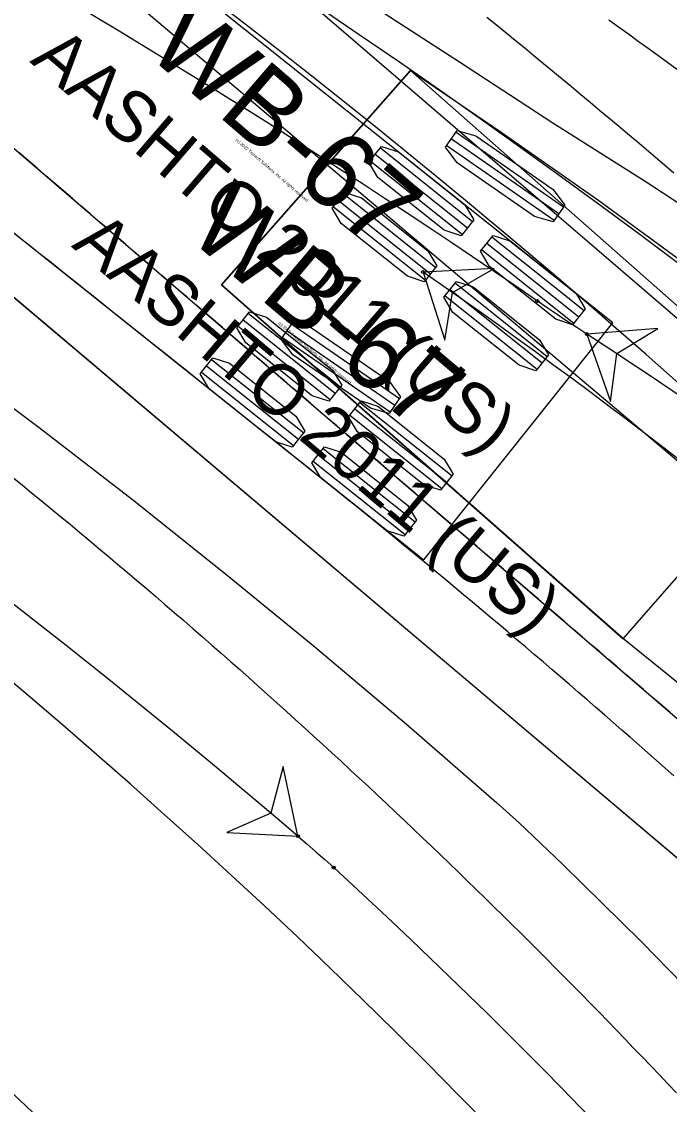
# Model space of a CAD drawing. Extents: x 2175591 to 2194071, y 76570 to 86955.
# Drawn here: x 2192868.19 to 2192886.34, y 86887.24 to 86917.59 of the extents above; entities that cross this region are included whole.
import ezdxf

# ---------------------------------------------------------------- set-up
doc = ezdxf.new("R2010")
doc.units = 0
doc.layers.add('-NOPLT', color=7, linetype='Continuous')
doc.layers.add('C-UTIL-STRM-TEXT', color=7, linetype='Continuous')

msp = doc.modelspace()

# ---------------------------------------------------------------- linework, layer by layer
at = {"layer": '-NOPLT'}
for p, q in [((2192884.758, 86909.148), (2192843.326, 86942.199)), ((2192838.025, 86935.555), (2192879.458, 86902.504)), ((2192898.388, 86899.098), (2192858.201, 86933.653)), ((2192852.66, 86927.208), (2192892.847, 86892.653)), ((2192878.244, 86914.052), (2192880.824, 86911.994)), ((2192877.958, 86913.693), (2192880.538, 86911.635)), ((2192878.101, 86913.873), (2192880.681, 86911.815)), ((2192877.072, 86912.583), (2192879.652, 86910.525)), ((2192877.215, 86912.762), (2192879.795, 86910.704)), ((2192876.929, 86912.403), (2192879.509, 86910.346)), ((2192881.228, 86911.378), (2192883.808, 86909.32)), ((2192881.371, 86911.557), (2192883.951, 86909.499)), ((2192881.085, 86911.199), (2192883.665, 86909.141)), ((2192880.199, 86910.088), (2192882.779, 86908.03)), ((2192880.342, 86910.267), (2192882.922, 86908.209)), ((2192880.056, 86909.909), (2192882.636, 86907.851)), ((2192874.401, 86909.234), (2192876.981, 86907.176)), ((2192874.544, 86909.413), (2192877.124, 86907.355)), ((2192879.458, 86902.504), (2192884.758, 86909.148)), ((2192874.258, 86909.055), (2192876.838, 86906.997)), ((2192873.372, 86907.944), (2192875.952, 86905.886)), ((2192873.515, 86908.123), (2192876.095, 86906.066)), ((2192873.229, 86907.765), (2192875.809, 86905.707)), ((2192877.528, 86906.74), (2192880.108, 86904.682)), ((2192877.671, 86906.919), (2192880.251, 86904.861)), ((2192877.385, 86906.561), (2192879.965, 86904.503)), ((2192876.642, 86905.629), (2192879.222, 86903.571)), ((2192876.356, 86905.271), (2192878.936, 86903.213)), ((2192876.499, 86905.45), (2192879.079, 86903.392))]:
    msp.add_line(p, q, dxfattribs=at)
for points in [[(2192881.23, 86917.714), (2192881.495, 86917.5), (2192881.76, 86917.285), (2192882.024, 86917.07), (2192882.288, 86916.854), (2192882.552, 86916.638), (2192882.815, 86916.422), (2192883.078, 86916.205), (2192883.341, 86915.988), (2192883.603, 86915.77), (2192883.865, 86915.552), (2192884.127, 86915.334), (2192884.388, 86915.115), (2192884.649, 86914.896), (2192884.91, 86914.677), (2192885.171, 86914.457), (2192885.431, 86914.237), (2192885.691, 86914.016), (2192885.95, 86913.795), (2192886.209, 86913.574), (2192886.468, 86913.352)], [(2192884.641, 86917.646), (2192884.918, 86917.448), (2192885.194, 86917.249), (2192885.47, 86917.049), (2192885.745, 86916.849), (2192886.021, 86916.649), (2192886.296, 86916.449), (2192886.571, 86916.248)], [(2192886.351, 86898.238), (2192886.106, 86898.449), (2192885.861, 86898.66), (2192885.616, 86898.87), (2192885.371, 86899.081), (2192885.126, 86899.292), (2192884.881, 86899.503), (2192884.635, 86899.713), (2192884.39, 86899.924), (2192884.145, 86900.135), (2192883.9, 86900.346), (2192883.655, 86900.557), (2192883.409, 86900.768), (2192883.164, 86900.979), (2192882.919, 86901.19), (2192882.673, 86901.401), (2192882.428, 86901.612), (2192882.182, 86901.823), (2192881.937, 86902.034), (2192881.692, 86902.245), (2192881.446, 86902.456), (2192881.201, 86902.667), (2192880.955, 86902.878), (2192880.71, 86903.089), (2192880.464, 86903.3), (2192880.218, 86903.512), (2192879.973, 86903.723), (2192879.727, 86903.934), (2192879.481, 86904.145), (2192879.235, 86904.357), (2192878.989, 86904.568), (2192878.744, 86904.779), (2192878.498, 86904.991), (2192878.252, 86905.202), (2192878.006, 86905.414), (2192877.76, 86905.625), (2192877.514, 86905.837), (2192877.268, 86906.049), (2192877.021, 86906.26), (2192876.775, 86906.472), (2192876.529, 86906.684), (2192876.283, 86906.896), (2192876.036, 86907.108), (2192875.79, 86907.319), (2192875.543, 86907.531), (2192875.297, 86907.743), (2192875.05, 86907.956), (2192874.803, 86908.167), (2192874.557, 86908.38), (2192874.31, 86908.592), (2192874.063, 86908.804), (2192873.816, 86909.016), (2192873.569, 86909.229), (2192873.322, 86909.441), (2192873.075, 86909.654), (2192872.828, 86909.866), (2192872.581, 86910.079), (2192872.334, 86910.291), (2192872.086, 86910.504), (2192871.839, 86910.716), (2192871.592, 86910.929), (2192871.344, 86911.142), (2192871.097, 86911.355), (2192870.849, 86911.567), (2192870.602, 86911.78), (2192870.354, 86911.993), (2192870.107, 86912.206), (2192869.859, 86912.419), (2192869.611, 86912.632), (2192869.364, 86912.845), (2192869.116, 86913.058), (2192868.868, 86913.271), (2192868.621, 86913.484), (2192868.373, 86913.697), (2192868.125, 86913.91)], [(2192886.468, 86896.451), (2192886.225, 86896.666), (2192885.982, 86896.88), (2192885.739, 86897.095), (2192885.496, 86897.309), (2192885.252, 86897.523), (2192885.008, 86897.736), (2192884.764, 86897.95), (2192884.52, 86898.162), (2192884.275, 86898.375), (2192884.03, 86898.587), (2192883.785, 86898.799), (2192883.54, 86899.011), (2192883.294, 86899.222), (2192883.048, 86899.434), (2192882.802, 86899.644), (2192882.556, 86899.855), (2192882.309, 86900.065), (2192882.062, 86900.275), (2192881.815, 86900.484), (2192881.568, 86900.693), (2192881.32, 86900.902), (2192881.072, 86901.111), (2192880.824, 86901.319), (2192880.575, 86901.527), (2192880.327, 86901.734), (2192880.078, 86901.942), (2192879.829, 86902.149), (2192879.579, 86902.355), (2192879.329, 86902.561), (2192879.079, 86902.767), (2192878.829, 86902.973), (2192878.579, 86903.178), (2192878.328, 86903.383), (2192878.077, 86903.588), (2192877.826, 86903.792), (2192877.574, 86903.997), (2192877.323, 86904.2), (2192877.071, 86904.404), (2192876.818, 86904.607), (2192876.566, 86904.809), (2192876.313, 86905.012), (2192876.06, 86905.214), (2192875.807, 86905.416), (2192875.554, 86905.618), (2192875.301, 86905.819), (2192875.048, 86906.021), (2192874.795, 86906.223), (2192874.542, 86906.425), (2192874.289, 86906.627), (2192874.036, 86906.829), (2192873.783, 86907.03), (2192873.53, 86907.232), (2192873.277, 86907.434), (2192873.024, 86907.636), (2192872.771, 86907.838), (2192872.518, 86908.04), (2192872.265, 86908.241), (2192872.012, 86908.443), (2192871.759, 86908.645), (2192871.506, 86908.847), (2192871.253, 86909.049), (2192871, 86909.25), (2192870.747, 86909.452), (2192870.494, 86909.654), (2192870.241, 86909.856), (2192869.988, 86910.058), (2192869.735, 86910.259), (2192869.482, 86910.461), (2192869.229, 86910.663), (2192868.976, 86910.865), (2192868.723, 86911.067), (2192868.47, 86911.269), (2192868.217, 86911.47), (2192867.964, 86911.672)], [(2192867.931, 86904.827), (2192868.201, 86904.607), (2192868.471, 86904.387), (2192868.74, 86904.167), (2192869.009, 86903.946), (2192869.278, 86903.725), (2192869.546, 86903.503), (2192869.814, 86903.281), (2192870.081, 86903.058), (2192870.348, 86902.835), (2192870.615, 86902.611), (2192870.881, 86902.387), (2192871.146, 86902.162), (2192871.412, 86901.937), (2192871.676, 86901.711), (2192871.941, 86901.485), (2192872.205, 86901.258), (2192872.469, 86901.031), (2192872.732, 86900.804), (2192872.995, 86900.576), (2192873.257, 86900.347), (2192873.519, 86900.118), (2192873.78, 86899.888), (2192874.041, 86899.658), (2192874.302, 86899.428), (2192874.562, 86899.197), (2192874.822, 86898.965), (2192875.082, 86898.733), (2192875.341, 86898.501), (2192875.599, 86898.268), (2192875.857, 86898.035), (2192876.115, 86897.801), (2192876.372, 86897.566), (2192876.629, 86897.332), (2192876.885, 86897.096), (2192877.141, 86896.861), (2192877.397, 86896.624), (2192877.652, 86896.388), (2192877.907, 86896.151), (2192878.161, 86895.913), (2192878.415, 86895.675), (2192878.668, 86895.436), (2192878.921, 86895.197), (2192879.174, 86894.958), (2192879.426, 86894.718), (2192879.677, 86894.477), (2192879.928, 86894.237), (2192880.179, 86893.995), (2192880.429, 86893.754), (2192880.679, 86893.511), (2192880.929, 86893.269), (2192881.178, 86893.025), (2192881.426, 86892.782), (2192881.674, 86892.538), (2192881.922, 86892.293), (2192882.169, 86892.048), (2192882.416, 86891.803), (2192882.662, 86891.557), (2192882.908, 86891.311), (2192883.153, 86891.064), (2192883.398, 86890.817), (2192883.643, 86890.569), (2192883.887, 86890.321), (2192884.13, 86890.072), (2192884.373, 86889.823), (2192884.616, 86889.574), (2192884.858, 86889.324), (2192885.1, 86889.073), (2192885.341, 86888.822), (2192885.582, 86888.571), (2192885.822, 86888.319), (2192886.062, 86888.067), (2192886.302, 86887.815), (2192886.541, 86887.562)]]:
    msp.add_lwpolyline(points, dxfattribs=at)
for points in [[(2192877.923, 86913.649), (2192878.279, 86914.096), (2192878.748, 86913.943), (2192880.606, 86912.461), (2192880.859, 86912.038), (2192880.503, 86911.591), (2192880.034, 86911.744), (2192878.176, 86913.226)], [(2192876.894, 86912.359), (2192877.251, 86912.806), (2192877.719, 86912.653), (2192879.577, 86911.171), (2192879.83, 86910.748), (2192879.474, 86910.301), (2192879.005, 86910.455), (2192877.148, 86911.936)], [(2192881.05, 86911.155), (2192881.406, 86911.602), (2192881.875, 86911.448), (2192883.732, 86909.967), (2192883.986, 86909.544), (2192883.629, 86909.097), (2192883.161, 86909.25), (2192881.303, 86910.732)], [(2192880.021, 86909.865), (2192880.377, 86910.312), (2192880.846, 86910.158), (2192882.704, 86908.677), (2192882.957, 86908.254), (2192882.601, 86907.807), (2192882.132, 86907.96), (2192880.274, 86909.442)], [(2192874.223, 86909.011), (2192874.579, 86909.458), (2192875.048, 86909.304), (2192876.905, 86907.823), (2192877.159, 86907.4), (2192876.802, 86906.953), (2192876.334, 86907.106), (2192874.476, 86908.588)], [(2192873.194, 86907.721), (2192873.55, 86908.168), (2192874.019, 86908.015), (2192875.877, 86906.533), (2192876.13, 86906.11), (2192875.774, 86905.663), (2192875.305, 86905.816), (2192873.447, 86907.298)], [(2192877.35, 86906.516), (2192877.706, 86906.963), (2192878.175, 86906.81), (2192880.032, 86905.328), (2192880.286, 86904.905), (2192879.929, 86904.458), (2192879.461, 86904.612), (2192877.603, 86906.093)], [(2192876.321, 86905.226), (2192876.677, 86905.673), (2192877.146, 86905.52), (2192879.003, 86904.038), (2192879.257, 86903.616), (2192878.9, 86903.168), (2192878.432, 86903.322), (2192876.574, 86904.804)]]:
    msp.add_lwpolyline(points, close=True, dxfattribs=at)
for centre, radius, start, end in [((2192733.134, 86734.566), 231.18, 31.07167, 66.3451), ((2192748.446, 86757.375), 185.351, 28.75355, 79.22293), ((2192746.129, 86724.49), 233.336, 23.25976, 66.11585)]:
    msp.add_arc(centre, radius, start, end, dxfattribs=at)
at = {"layer": 'C-UTIL-STRM-TEXT'}
for p, q in [((2192899.695, 86894.172), (2192859.224, 86928.392)), ((2192853.736, 86921.902), (2192894.207, 86887.681)), ((2192879.084, 86916.218), (2192873.793, 86910.218)), ((2192890.334, 86906.296), (2192879.084, 86916.218)), ((2192880.235, 86914.308), (2192883.245, 86912.214)), ((2192880.365, 86914.496), (2192883.375, 86912.402)), ((2192880.104, 86914.119), (2192883.114, 86912.026)), ((2192873.793, 86910.218), (2192885.043, 86900.296)), ((2192873.793, 86910.218), (2192873.793, 86910.218)), ((2192875.629, 86908.922), (2192878.648, 86906.841)), ((2192875.759, 86909.111), (2192878.778, 86907.03)), ((2192875.499, 86908.734), (2192878.518, 86906.653)), ((2192885.043, 86900.296), (2192886.74, 86902.221))]:
    msp.add_line(p, q, dxfattribs=at)
for points in [[(2192917.573, 86863.028), (2192915.761, 86865.28), (2192913.888, 86867.533), (2192912.022, 86869.708), (2192910.323, 86871.631), (2192908.446, 86873.695), (2192906.547, 86875.724), (2192904.608, 86877.736), (2192902.637, 86879.722), (2192900.592, 86881.724), (2192898.512, 86883.702), (2192896.411, 86885.642), (2192894.283, 86887.552), (2192892.129, 86889.43), (2192855.115, 86920.736)], [(2192877.902, 86918.123), (2192880.493, 86916.45), (2192883.074, 86914.757), (2192885.663, 86913.122), (2192888.231, 86911.437), (2192890.762, 86909.709), (2192893.265, 86907.934), (2192895.503, 86906.286), (2192897.957, 86904.413), (2192900.389, 86902.485), (2192902.803, 86900.496), (2192905.181, 86898.462), (2192907.521, 86896.384), (2192908.676, 86895.329), (2192909.799, 86894.239), (2192910.865, 86893.103), (2192912.907, 86890.727), (2192916.943, 86885.948)], [(2192918.377, 86863.304), (2192888.843, 86897.193), (2192886.338, 86899.259), (2192885.072, 86900.273), (2192873.793, 86910.218), (2192879.084, 86916.218), (2192881.632, 86914.496), (2192884.364, 86912.575), (2192887.079, 86910.585), (2192889.766, 86908.535), (2192892.42, 86906.426), (2192895.034, 86904.264), (2192897.605, 86902.051), (2192900.132, 86899.788), (2192902.613, 86897.477), (2192905.048, 86895.117), (2192907.435, 86892.712), (2192909.773, 86890.261), (2192911.489, 86888.389), (2192912.039, 86887.745), (2192912.573, 86887.088), (2192913.091, 86886.416), (2192913.594, 86885.73), (2192920.735, 86875.173)], [(2192884.029, 86908.834), (2192883.75, 86909.016), (2192883.472, 86909.199), (2192883.194, 86909.384), (2192882.918, 86909.571), (2192882.643, 86909.759)], [(2192866.026, 86908.2), (2192868.679, 86906.211), (2192871.293, 86904.193), (2192873.903, 86902.116), (2192876.41, 86900.063), (2192878.973, 86897.9), (2192881.501, 86895.704), (2192882.133, 86895.138), (2192883.35, 86893.979), (2192885.561, 86891.8), (2192887.891, 86889.417), (2192890.175, 86886.989), (2192892.388, 86884.543), (2192894.575, 86882.031), (2192896.715, 86879.476), (2192898.805, 86876.88), (2192900.846, 86874.242), (2192902.837, 86871.564), (2192904.753, 86868.88), (2192906.622, 86866.154), (2192908.394, 86863.461), (2192910.036, 86860.863), (2192911.75, 86858.04), (2192912.594, 86856.603)], [(2192875.933, 86894.76), (2192876.187, 86894.543), (2192876.438, 86894.325), (2192876.688, 86894.104), (2192876.935, 86893.88)], [(2192894.581, 86854.444), (2192893.005, 86857.038), (2192891.384, 86859.579), (2192889.711, 86862.09), (2192887.995, 86864.563), (2192886.232, 86867.005), (2192884.418, 86869.414), (2192882.553, 86871.789), (2192880.637, 86874.127), (2192878.669, 86876.431), (2192876.653, 86878.698), (2192874.591, 86880.923), (2192872.629, 86882.961), (2192870.48, 86885.11), (2192868.285, 86887.223), (2192866.05, 86889.294)]]:
    msp.add_lwpolyline(points, dxfattribs=at)
for points in [[(2192880.071, 86914.073), (2192880.398, 86914.542), (2192880.918, 86914.391), (2192883.085, 86912.883), (2192883.408, 86912.448), (2192883.081, 86911.979), (2192882.561, 86912.131), (2192880.394, 86913.638)], [(2192879.438, 86910.572), (2192880.05, 86908.668), (2192880.261, 86910.003), (2192881.436, 86910.669)], [(2192875.467, 86908.687), (2192875.792, 86909.158), (2192876.312, 86909.008), (2192878.486, 86907.51), (2192878.811, 86907.077), (2192878.486, 86906.606), (2192877.966, 86906.755), (2192875.792, 86908.254)], [(2192884.029, 86908.834), (2192884.695, 86906.948), (2192884.867, 86908.289), (2192886.023, 86908.989)], [(2192875.933, 86894.76), (2192875.518, 86896.716), (2192875.173, 86895.409), (2192873.936, 86894.865)]]:
    msp.add_lwpolyline(points, close=True, dxfattribs=at)
for centre in [(2192879.438, 86910.572), (2192882.643, 86909.759), (2192882.643, 86909.759), (2192884.029, 86908.834), (2192884.029, 86908.834), (2192875.933, 86894.76), (2192875.933, 86894.76), (2192876.935, 86893.88), (2192876.935, 86893.88)]:
    msp.add_circle(centre, 0.0417, dxfattribs=at)
for centre, radius, start, end in [((2192752.314, 86720.717), 229.614, 55.41684, 67.13934), ((2192729.537, 86723.348), 225.419, 49.50064, 61.93177), ((2192783.659, 86772.261), 168.236, 41.2801, 55.29768), ((2192794.732, 86771.714), 163.633, 46.13506, 56.92649), ((2192763.098, 86769.778), 168.405, 31.34657, 47.47016)]:
    msp.add_arc(centre, radius, start, end, dxfattribs=at)

# ---------------------------------------------------------------- texts
at = {"layer": '-NOPLT'}
for s, height, p in [('WB-67', 2.125, (2192871.607, 86916.745)), ('AASHTO 2011 (US)', 1.41667, (2192868.399, 86916.468)), ('(c) 2022 Transoft Solutions, Inc. All rights reserved.', 0.085, (2192874.177, 86914.255))]:
    msp.add_text(s, height=height, rotation=319.3095, dxfattribs=at).set_placement(p)
at = {"layer": 'C-UTIL-STRM-TEXT'}
for s, height, p in [('WB-67', 2.125, (2192872.769, 86911.597)), ('AASHTO 2011 (US)', 1.41667, (2192869.563, 86911.292)), ('(c) 2019 Transoft Solutions, Inc. All rights reserved.', 0.085, (2192875.365, 86909.123))]:
    msp.add_text(s, height=height, rotation=319.7837, dxfattribs=at).set_placement(p)

doc.saveas('drawing.dxf')
